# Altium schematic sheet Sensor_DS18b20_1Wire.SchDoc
size A4; Organization: Altium Limited; Address1: L3, 12a Rodborough Rd; Address2: Frenchs Forest; Address3: NSW; Address4: Australia 2086
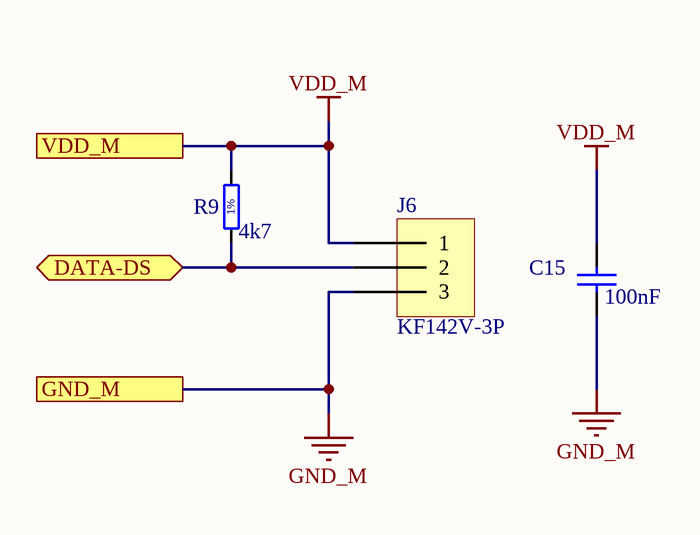
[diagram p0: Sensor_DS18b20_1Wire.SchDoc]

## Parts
C15  100nF  [CAPC1608X87N]
J6  KF142V-3P  [CON KF142V-3P-5.08]
R9  4k7  [RESC1608X55N]

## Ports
DATA-DS (bidir), GND_M, VDD_M

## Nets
GND_M: C15.1 J6.3 ; port GND_M
VDD_M: C15.2 J6.1 R9.2 ; port VDD_M
DATA-DS: J6.2 R9.1 ; port DATA-DS

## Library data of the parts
C15 = CC0603_100NF_50V_10%_X7R: Non-polarised capacitor; Part Description: SMD Multilayer Chip Ceramic Capacitor; Manufacturer: GENERIC; Manufacturer1 Part Number: 223858615649; Voltage: 50V; TC: X7R; Tolerance: ±10%; Table: Capacitors SMD
J6 = CON KF142V-3P-5.08
R9 = R0603_4K7_1%_0.1W_100PPM: Resistor - 1%; Part Description: General Purpose Thick Film Chip Resistor; Manufacturer: GENERIC; Manufacturer1 Part Number: NRC06F4701TRF; Power: 0.1W; TC: ±100ppm/°C; Table: Resistors SMD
